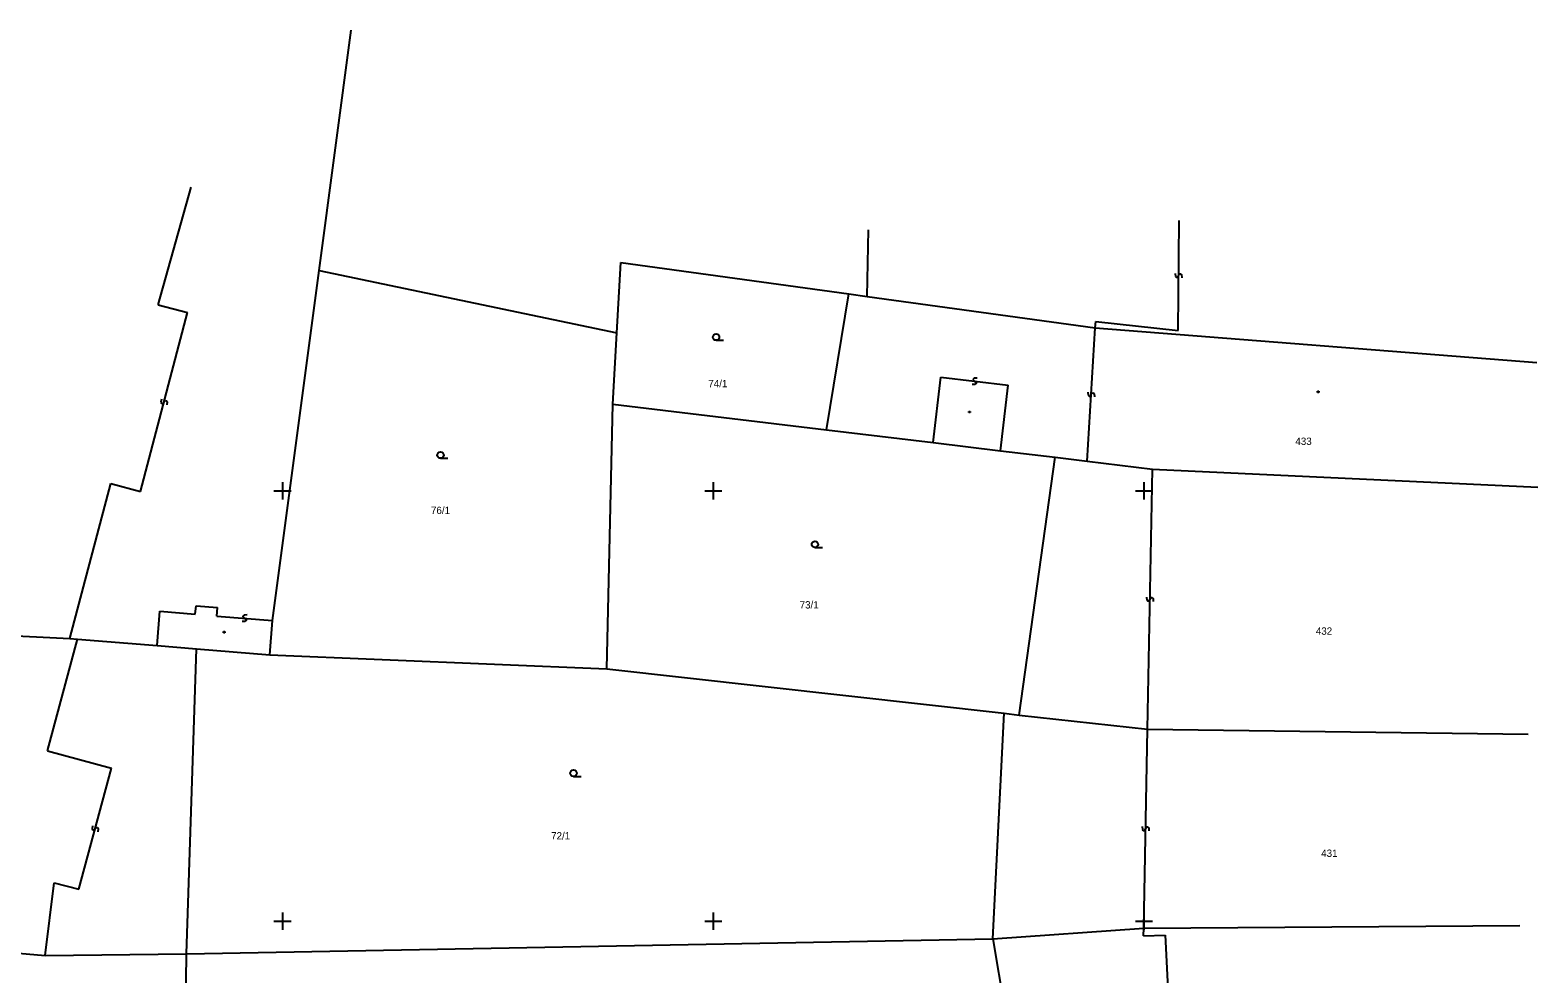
# Model space of a CAD drawing. Extents: x -492811 to -492366, y -1127107 to -1126748.
# Drawn here: x -492491.7 to -492421.7, y -1126802.4 to -1126758.6 of the extents above; entities that cross this region are included whole.
import ezdxf

# ---------------------------------------------------------------- set-up
doc = ezdxf.new("R2010")
doc.units = 0
doc.layers.add('katastrální mapa', color=7, linetype='Continuous')
doc.layers.add('síť', color=7, linetype='Continuous')

msp = doc.modelspace()

# ---------------------------------------------------------------- linework, layer by layer
at = {"layer": 'katastrální mapa'}
for p, q in [((-492478.3, -1126769.77), (-492476.81, -1126758.6)), ((-492485.77, -1126771.36), (-492484.24, -1126765.9)), ((-492438.42, -1126772.55), (-492438.37, -1126767.45)), ((-492452.85, -1126770.97), (-492452.79, -1126767.88)), ((-492480.47, -1126786.03), (-492478.3, -1126769.77)), ((-492478.3, -1126769.77), (-492464.48, -1126772.66)), ((-492464.48, -1126772.66), (-492464.3, -1126769.39)), ((-492464.3, -1126769.39), (-492453.7, -1126770.85)), ((-492438.55, -1126769.9), (-492438.54, -1126770.04)), ((-492438.54, -1126770.04), (-492438.5, -1126770.08)), ((-492438.5, -1126770.08), (-492438.46, -1126770.08)), ((-492438.46, -1126770.08), (-492438.42, -1126770.04)), ((-492438.42, -1126770.04), (-492438.37, -1126769.96)), ((-492438.37, -1126769.96), (-492438.33, -1126769.92)), ((-492438.33, -1126769.92), (-492438.29, -1126769.92)), ((-492438.29, -1126769.92), (-492438.25, -1126769.96)), ((-492438.25, -1126769.96), (-492438.24, -1126770.1)), ((-492454.75, -1126777.17), (-492453.7, -1126770.85)), ((-492453.7, -1126770.85), (-492452.85, -1126770.97)), ((-492452.85, -1126770.97), (-492442.26, -1126772.43)), ((-492486.6, -1126780.03), (-492484.41, -1126771.72)), ((-492485.77, -1126771.36), (-492484.41, -1126771.72)), ((-492442.64, -1126778.62), (-492442.26, -1126772.43)), ((-492442.26, -1126772.43), (-492442.24, -1126772.13)), ((-492442.26, -1126772.43), (-492421.75, -1126774.04)), ((-492442.24, -1126772.13), (-492438.42, -1126772.55)), ((-492464.66, -1126775.98), (-492464.48, -1126772.66)), ((-492459.87, -1126773.01), (-492459.52, -1126773.01)), ((-492449.79, -1126777.76), (-492449.43, -1126774.73)), ((-492449.43, -1126774.73), (-492446.3, -1126775.1)), ((-492447.84, -1126775.06), (-492447.98, -1126775.06)), ((-492447.93, -1126774.81), (-492447.94, -1126774.85)), ((-492447.94, -1126774.85), (-492447.9, -1126774.89)), ((-492447.89, -1126774.77), (-492447.93, -1126774.81)), ((-492447.9, -1126774.89), (-492447.83, -1126774.94)), ((-492447.75, -1126774.77), (-492447.89, -1126774.77)), ((-492447.8, -1126775.02), (-492447.84, -1126775.06)), ((-492447.83, -1126774.94), (-492447.79, -1126774.98)), ((-492447.79, -1126774.98), (-492447.8, -1126775.02)), ((-492446.66, -1126778.14), (-492446.3, -1126775.1)), ((-492431.94, -1126775.37), (-492431.88, -1126775.37)), ((-492431.94, -1126775.43), (-492431.94, -1126775.37)), ((-492431.88, -1126775.37), (-492431.88, -1126775.43)), ((-492485.63, -1126775.74), (-492485.65, -1126775.88)), ((-492485.65, -1126775.88), (-492485.62, -1126775.93)), ((-492485.62, -1126775.93), (-492485.58, -1126775.94)), ((-492485.58, -1126775.94), (-492485.53, -1126775.91)), ((-492485.53, -1126775.91), (-492485.48, -1126775.84)), ((-492485.48, -1126775.84), (-492485.43, -1126775.81)), ((-492485.43, -1126775.81), (-492485.39, -1126775.82)), ((-492485.39, -1126775.82), (-492485.36, -1126775.87)), ((-492485.36, -1126775.87), (-492485.38, -1126776.01)), ((-492464.95, -1126788.28), (-492464.66, -1126775.98)), ((-492464.66, -1126775.98), (-492454.75, -1126777.17)), ((-492442.6, -1126775.42), (-492442.59, -1126775.56)), ((-492442.59, -1126775.56), (-492442.55, -1126775.6)), ((-492442.55, -1126775.6), (-492442.51, -1126775.6)), ((-492442.51, -1126775.6), (-492442.47, -1126775.56)), ((-492442.47, -1126775.56), (-492442.43, -1126775.49)), ((-492442.43, -1126775.49), (-492442.39, -1126775.45)), ((-492442.39, -1126775.45), (-492442.35, -1126775.45)), ((-492442.35, -1126775.45), (-492442.31, -1126775.49)), ((-492442.31, -1126775.49), (-492442.3, -1126775.63)), ((-492431.88, -1126775.43), (-492431.94, -1126775.43)), ((-492448.13, -1126776.31), (-492448.07, -1126776.31)), ((-492448.13, -1126776.37), (-492448.13, -1126776.31)), ((-492448.07, -1126776.37), (-492448.13, -1126776.37)), ((-492448.07, -1126776.31), (-492448.07, -1126776.37)), ((-492454.75, -1126777.17), (-492449.79, -1126777.76)), ((-492449.79, -1126777.76), (-492446.66, -1126778.14)), ((-492446.66, -1126778.14), (-492444.13, -1126778.44)), ((-492472.67, -1126778.49), (-492472.32, -1126778.49)), ((-492445.8, -1126790.42), (-492444.13, -1126778.44)), ((-492444.13, -1126778.44), (-492442.64, -1126778.62)), ((-492442.64, -1126778.62), (-492439.61, -1126779)), ((-492439.84, -1126791.08), (-492439.61, -1126779)), ((-492439.61, -1126779), (-492421.71, -1126779.84)), ((-492489.88, -1126786.86), (-492487.97, -1126779.66)), ((-492487.97, -1126779.66), (-492486.6, -1126780.03)), ((-492455.28, -1126782.64), (-492454.93, -1126782.64)), ((-492439.88, -1126784.94), (-492439.87, -1126785.08)), ((-492439.87, -1126785.08), (-492439.83, -1126785.12)), ((-492439.83, -1126785.12), (-492439.79, -1126785.12)), ((-492439.79, -1126785.12), (-492439.75, -1126785.08)), ((-492439.75, -1126785.08), (-492439.7, -1126785)), ((-492439.7, -1126785), (-492439.66, -1126784.96)), ((-492439.66, -1126784.96), (-492439.62, -1126784.96)), ((-492439.62, -1126784.96), (-492439.58, -1126785)), ((-492439.58, -1126785), (-492439.57, -1126785.14)), ((-492485.83, -1126787.19), (-492485.7, -1126785.6)), ((-492485.7, -1126785.6), (-492484.06, -1126785.73)), ((-492484.06, -1126785.73), (-492484.02, -1126785.34)), ((-492484.02, -1126785.34), (-492483.03, -1126785.42)), ((-492483.06, -1126785.82), (-492483.03, -1126785.42)), ((-492483.06, -1126785.82), (-492480.47, -1126786.03)), ((-492481.79, -1126785.78), (-492481.84, -1126785.82)), ((-492481.84, -1126785.82), (-492481.84, -1126785.86)), ((-492481.84, -1126785.86), (-492481.8, -1126785.9)), ((-492481.65, -1126785.77), (-492481.79, -1126785.78)), ((-492503.68, -1126786.2), (-492489.88, -1126786.86)), ((-492482.74, -1126786.54), (-492482.68, -1126786.54)), ((-492482.74, -1126786.6), (-492482.74, -1126786.54)), ((-492482.68, -1126786.54), (-492482.68, -1126786.6)), ((-492481.74, -1126786.07), (-492481.88, -1126786.08)), ((-492481.8, -1126785.9), (-492481.73, -1126785.95)), ((-492481.69, -1126786.03), (-492481.74, -1126786.07)), ((-492481.73, -1126785.95), (-492481.69, -1126785.99)), ((-492481.69, -1126785.99), (-492481.69, -1126786.03)), ((-492480.6, -1126787.63), (-492480.47, -1126786.03)), ((-492490.92, -1126792.09), (-492489.53, -1126786.89)), ((-492489.88, -1126786.86), (-492489.53, -1126786.89)), ((-492489.53, -1126786.89), (-492485.83, -1126787.19)), ((-492485.83, -1126787.19), (-492484, -1126787.34)), ((-492482.68, -1126786.6), (-492482.74, -1126786.6)), ((-492484.46, -1126801.52), (-492484, -1126787.34)), ((-492484, -1126787.34), (-492480.6, -1126787.63)), ((-492480.6, -1126787.63), (-492464.95, -1126788.28)), ((-492464.95, -1126788.28), (-492446.5, -1126790.34)), ((-492447.02, -1126800.81), (-492446.5, -1126790.34)), ((-492446.5, -1126790.34), (-492445.8, -1126790.42)), ((-492445.8, -1126790.42), (-492439.84, -1126791.08)), ((-492440.01, -1126800.32), (-492439.84, -1126791.08)), ((-492439.84, -1126791.08), (-492422.16, -1126791.31)), ((-492490.92, -1126792.09), (-492487.95, -1126792.89)), ((-492489.46, -1126798.51), (-492487.95, -1126792.89)), ((-492466.49, -1126793.27), (-492466.14, -1126793.27)), ((-492488.83, -1126795.56), (-492488.85, -1126795.7)), ((-492488.85, -1126795.7), (-492488.82, -1126795.75)), ((-492488.73, -1126795.73), (-492488.68, -1126795.67)), ((-492488.68, -1126795.67), (-492488.63, -1126795.64)), ((-492488.63, -1126795.64), (-492488.59, -1126795.65)), ((-492488.59, -1126795.65), (-492488.56, -1126795.7)), ((-492488.56, -1126795.7), (-492488.58, -1126795.84)), ((-492440.08, -1126795.6), (-492440.07, -1126795.74)), ((-492439.95, -1126795.74), (-492439.9, -1126795.66)), ((-492439.9, -1126795.66), (-492439.86, -1126795.62)), ((-492439.86, -1126795.62), (-492439.82, -1126795.62)), ((-492439.82, -1126795.62), (-492439.78, -1126795.66)), ((-492439.78, -1126795.66), (-492439.77, -1126795.8)), ((-492488.82, -1126795.75), (-492488.78, -1126795.76)), ((-492488.78, -1126795.76), (-492488.73, -1126795.73)), ((-492440.07, -1126795.74), (-492440.03, -1126795.78)), ((-492440.03, -1126795.78), (-492439.99, -1126795.78)), ((-492439.99, -1126795.78), (-492439.95, -1126795.74)), ((-492491.03, -1126801.59), (-492490.6, -1126798.21)), ((-492490.6, -1126798.21), (-492489.46, -1126798.51)), ((-492447.02, -1126800.81), (-492440.01, -1126800.32)), ((-492440.02, -1126800.68), (-492440.01, -1126800.32)), ((-492440.01, -1126800.32), (-492422.54, -1126800.19)), ((-492484.46, -1126801.52), (-492447.02, -1126800.81)), ((-492447.02, -1126800.81), (-492445.55, -1126809.54)), ((-492440.02, -1126800.68), (-492439.02, -1126800.64)), ((-492439.02, -1126800.64), (-492438.47, -1126811.53)), ((-492493.16, -1126801.41), (-492491.03, -1126801.59)), ((-492491.03, -1126801.59), (-492484.46, -1126801.52)), ((-492484.66, -1126817.9), (-492484.46, -1126801.52))]:
    msp.add_line(p, q, dxfattribs=at)
for centre in [(-492459.87, -1126772.86), (-492472.67, -1126778.34), (-492455.28, -1126782.49), (-492466.49, -1126793.12)]:
    msp.add_circle(centre, 0.15, dxfattribs=at)
at = {"layer": 'síť'}
for p, q in [((-492480.4, -1126780), (-492479.6, -1126780)), ((-492480, -1126779.6), (-492480, -1126780.4)), ((-492460.4, -1126780), (-492459.6, -1126780)), ((-492460, -1126779.6), (-492460, -1126780.4)), ((-492440.4, -1126780), (-492439.6, -1126780)), ((-492440, -1126779.6), (-492440, -1126780.4)), ((-492480, -1126799.6), (-492480, -1126800.4)), ((-492460, -1126799.6), (-492460, -1126800.4)), ((-492440, -1126799.6), (-492440, -1126800.4)), ((-492480.4, -1126800), (-492479.6, -1126800)), ((-492460.4, -1126800), (-492459.6, -1126800)), ((-492440.4, -1126800), (-492439.6, -1126800))]:
    msp.add_line(p, q, dxfattribs=at)

# ---------------------------------------------------------------- texts
at = {"layer": 'katastrální mapa'}
for s, p in [('74/1', (-492460.23, -1126775.19)), ('433', (-492432.97, -1126777.87)), ('76/1', (-492473.11, -1126781.08)), ('73/1', (-492455.99, -1126785.47)), ('432', (-492432.02, -1126786.69)), ('72/1', (-492467.53, -1126796.2)), ('431', (-492431.77, -1126797.01))]:
    msp.add_text(s, height=0.34, dxfattribs=at).set_placement(p)

doc.saveas('drawing.dxf')
